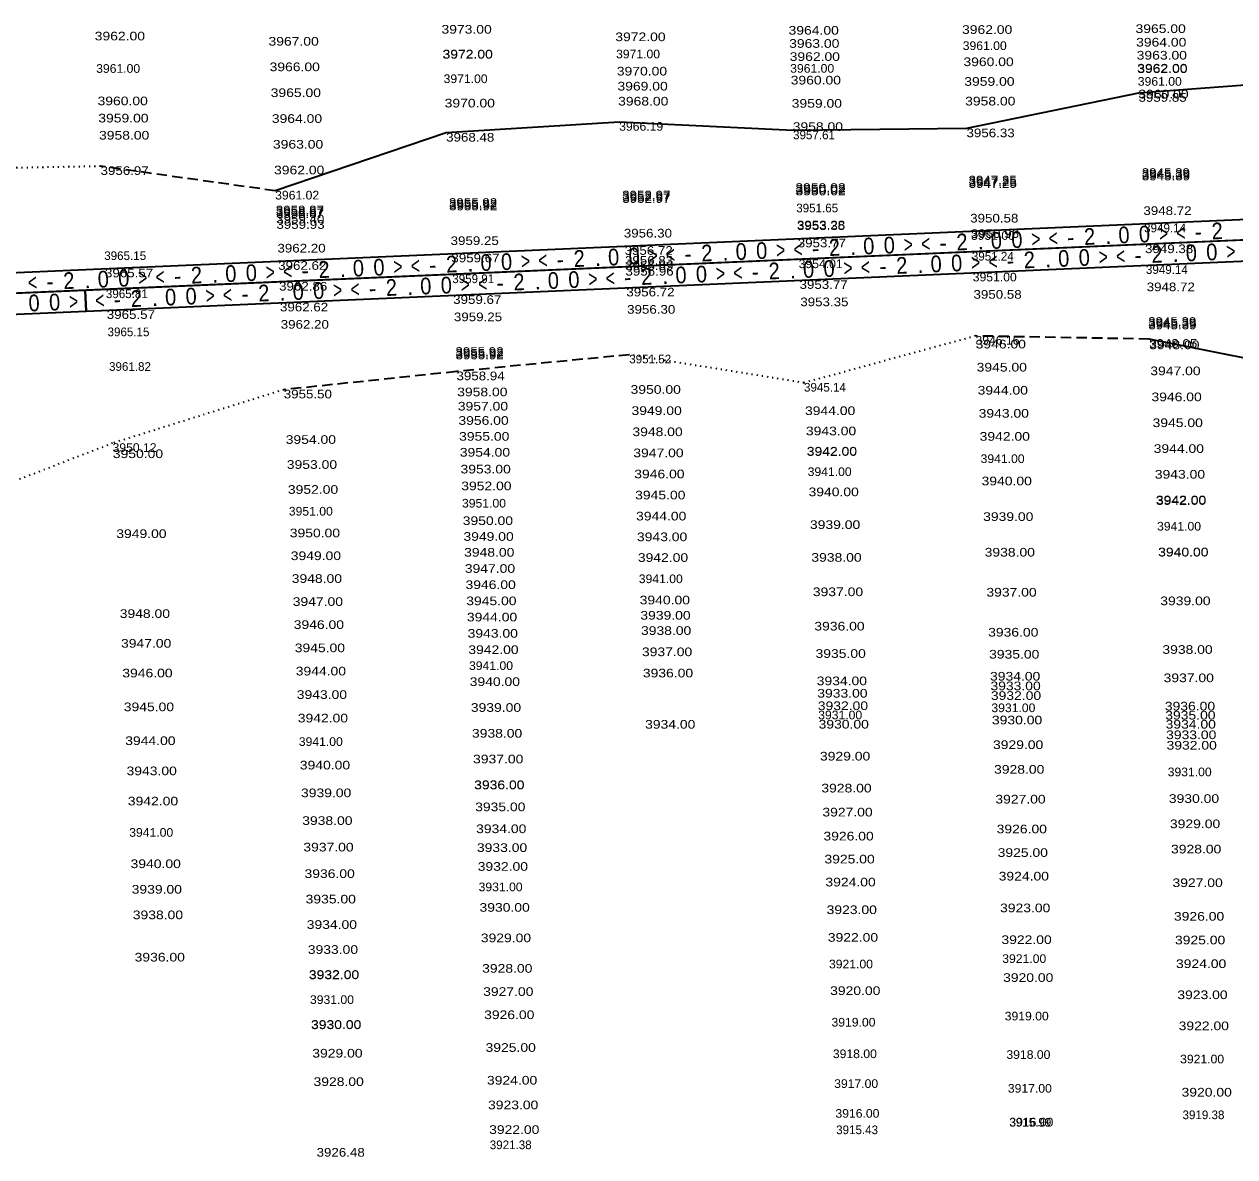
# Model space of a CAD drawing. Extents: x 49942 to 56479, y 47140 to 53283.
# Drawn here: x 52645 to 53343, y 49270 to 49923 of the extents above; entities that cross this region are included whole.
import ezdxf
from ezdxf.enums import TextEntityAlignment as Align

# ---------------------------------------------------------------- set-up
doc = ezdxf.new("R2010")
doc.units = 0
doc.header["$LTSCALE"] = 2
doc.linetypes.add('DOTTED', pattern=[1.5, 0.3, -1.2])
doc.linetypes.add('MEDIUM_DASHED', pattern=[4.5, 3, -1.5])
doc.layers.add('29', color=7, linetype='Continuous')
doc.layers.add('59', color=7, linetype='Continuous', lineweight=35)
doc.layers.add('63', color=7, linetype='Continuous', lineweight=35)

msp = doc.modelspace()

# ---------------------------------------------------------------- linework, layer by layer
at = {"layer": '59'}
for p, q in [((53387.529, 49890.602), (53287.754, 49883.256)), ((53287.754, 49883.256), (53188.546, 49862.795)), ((52988.196, 49866.565), (52888.374, 49860.274)), ((53088.503, 49861.631), (52988.196, 49866.565)), ((53188.546, 49862.795), (53088.503, 49861.631)), ((52888.374, 49860.274), (52789.726, 49826.892)), ((53394.861, 49721.266), (53293.897, 49741.36))]:
    msp.add_line(p, q, dxfattribs=at)
at = {"layer": '59', "linetype": 'DOTTED'}
for p, q in [((52689.019, 49841.052), (52589.011, 49839.074)), ((53193.726, 49743.159), (53094.804, 49716.091)), ((53094.804, 49716.091), (52994.006, 49732.374)), ((52794.693, 49712.17), (52695.936, 49681.3)), ((52695.936, 49681.3), (52597.493, 49643.178))]:
    msp.add_line(p, q, dxfattribs=at)
at = {"layer": '59', "linetype": 'MEDIUM_DASHED'}
for p, q in [((52789.726, 49826.892), (52689.019, 49841.052)), ((53293.897, 49741.36), (53193.726, 49743.159)), ((52994.006, 49732.374), (52894.334, 49722.632)), ((52894.334, 49722.632), (52794.693, 49712.17))]:
    msp.add_line(p, q, dxfattribs=at)
at = {"layer": '63'}
for points in [[(52494.091, 49773.45), (53576.866, 49820.33), (53577.385, 49808.342), (52494.61, 49761.461)], [(52680.665, 49757.505), (53728.923, 49802.891), (53728.404, 49814.88), (52680.146, 49769.494)]]:
    msp.add_lwpolyline(points, close=True, dxfattribs=at)
msp.add_lwpolyline([(52476.574, 49748.669), (52680.665, 49757.505), (52680.146, 49769.494), (52476.055, 49760.658)], dxfattribs=at)

# ---------------------------------------------------------------- texts
at = {"layer": '29'}
for s, width, p in [('3962.00', 1.2, (52685.659, 49913.662)), ('3973.00', 1.2, (52885.678, 49917.55)), ('3972.00', 1.2, (52985.959, 49913.218)), ('3964.00', 1.2, (53085.891, 49916.963)), ('3962.00', 1.2, (53185.965, 49917.411)), ('3965.00', 1.2, (53286.037, 49917.917)), ('3967.00', 1.2, (52785.884, 49910.637)), ('3963.00', 1.2, (53086.219, 49909.383)), ('3961.00', 1.05, (53186.367, 49908.114)), ('3964.00', 1.2, (53286.375, 49910.097)), ('3972.00', 1.2, (52886.296, 49903.27)), ('3972.00', 1.2, (52886.299, 49903.193)), ('3972.00', 1.2, (52886.303, 49903.117)), ('3971.00', 1.05, (52986.388, 49903.312)), ('3962.00', 1.2, (53086.547, 49901.804)), ('3960.00', 1.2, (53186.77, 49898.818)), ('3963.00', 1.2, (53286.7, 49902.597)), ('3961.00', 1.05, (52686.469, 49894.952)), ('3966.00', 1.2, (52786.521, 49895.901)), ('3970.00', 1.2, (52986.817, 49893.406)), ('3961.00', 1.05, (53086.841, 49895.019)), ('3962.00', 1.2, (53287.025, 49895.097)), ('3962.00', 1.2, (53287.031, 49894.963)), ('3962.00', 1.2, (53287.036, 49894.828)), ('3971.00', 1.05, (52886.912, 49889.051)), ('3969.00', 1.2, (52987.192, 49884.747)), ('3960.00', 1.2, (53087.135, 49888.233)), ('3959.00', 1.2, (53187.261, 49887.476)), ('3961.00', 1.05, (53287.354, 49887.5)), ('3965.00', 1.2, (52787.167, 49880.985)), ('3960.00', 1.2, (53287.671, 49880.172)), ('3959.85', 1.15, (53287.754, 49878.256)), ('3960.00', 1.2, (52687.279, 49876.241)), ('3970.00', 1.2, (52887.521, 49874.986)), ('3968.00', 1.2, (52987.567, 49876.089)), ('3959.00', 1.2, (53087.715, 49874.829)), ('3958.00', 1.2, (53187.752, 49876.133)), ('3959.00', 1.2, (52687.708, 49866.342)), ('3964.00', 1.2, (52787.813, 49866.069)), ('3958.00', 1.2, (52688.136, 49856.442)), ('3966.19', 1.05, (52988.196, 49861.565)), ('3958.00', 1.2, (53088.295, 49861.425)), ('3956.33', 1.15, (53188.546, 49857.795)), ('3963.00', 1.2, (52788.456, 49851.228)), ('3968.48', 1.15, (52888.374, 49855.274)), ('3956.97', 1.15, (52689.019, 49836.052)), ('3962.00', 1.2, (52789.098, 49836.388)), ('3945.39', 1.15, (53289.63, 49834.924)), ('3947.25', 1.15, (53189.724, 49830.598)), ('3947.25', 1.15, (53189.767, 49829.599)), ('3947.25', 1.15, (53189.81, 49828.6)), ('3945.39', 1.15, (53289.673, 49833.925)), ('3945.39', 1.15, (53289.717, 49832.926)), ('3961.02', 1.05, (52789.726, 49821.892)), ('3952.97', 1.15, (52989.911, 49821.947)), ('3952.97', 1.15, (52989.954, 49820.948)), ('3950.02', 1.2, (53089.817, 49826.273)), ('3950.02', 1.2, (53089.861, 49825.274)), ('3950.02', 1.2, (53089.904, 49824.275)), ('3955.92', 1.15, (52890.004, 49817.621)), ('3955.92', 1.15, (52890.048, 49816.622)), ('3955.92', 1.15, (52890.091, 49815.623)), ('3952.97', 1.15, (52989.997, 49819.949)), ('3958.87', 1.15, (52790.098, 49813.296)), ('3958.87', 1.15, (52790.141, 49812.297)), ('3958.87', 1.15, (52790.184, 49811.298)), ('3959.40', 1.15, (52790.322, 49808.129)), ('3950.58', 1.15, (53190.675, 49808.619)), ('3948.72', 1.15, (53290.582, 49812.944)), ('3959.93', 1.15, (52790.459, 49804.961)), ('3956.30', 1.15, (52990.862, 49799.968)), ('3953.28', 1.15, (53090.751, 49804.7)), ('3953.35', 1.15, (53090.769, 49804.293)), ('3959.25', 1.15, (52890.956, 49795.642)), ('3953.77', 1.15, (53091.201, 49794.303)), ('3950.96', 1.15, (53191.06, 49799.72)), ('3951.00', 1.05, (53191.108, 49798.628)), ('3962.20', 1.15, (52791.05, 49791.316)), ('3956.72', 1.15, (52991.295, 49789.977)), ('3949.38', 1.15, (53291.533, 49790.965)), ('3962.62', 1.15, (52791.482, 49781.326)), ('3959.67', 1.15, (52891.389, 49785.651)), ('3956.83', 1.15, (52991.54, 49784.317)), ('3956.89', 1.15, (52991.677, 49781.153)), ('3954.01', 1.05, (53091.721, 49782.314)), ('3965.57', 1.15, (52691.576, 49777)), ('3956.96', 1.15, (52991.814, 49777.988)), ('3951.00', 1.05, (53192.146, 49774.651)), ('3962.86', 1.15, (52792.001, 49769.337)), ('3956.72', 1.15, (52992.333, 49765.999)), ('3953.77', 1.15, (53092.24, 49770.325)), ('3948.72', 1.15, (53292.485, 49768.986)), ('3959.67', 1.15, (52892.427, 49761.674)), ('3953.35', 1.15, (53092.672, 49760.334)), ('3950.58', 1.15, (53192.578, 49764.66)), ('3965.57', 1.15, (52692.614, 49753.023)), ('3962.62', 1.15, (52792.52, 49757.348)), ('3959.25', 1.15, (52892.859, 49751.683)), ('3956.30', 1.15, (52992.766, 49756.009)), ('3962.20', 1.15, (52792.953, 49747.358)), ('3945.39', 1.15, (53293.35, 49749.004)), ('3945.39', 1.15, (53293.393, 49748.005)), ('3945.39', 1.15, (53293.437, 49747.006)), ('3946.16', 1.05, (53193.726, 49738.158)), ('3955.92', 1.15, (52893.724, 49731.702)), ('3955.92', 1.15, (52893.768, 49730.703)), ('3946.00', 1.2, (53193.821, 49735.97)), ('3948.05', 1.15, (53293.897, 49736.361)), ('3948.00', 1.2, (53293.933, 49735.547)), ('3955.92', 1.15, (52893.811, 49729.704)), ('3958.94', 1.15, (52894.334, 49717.632)), ('3945.00', 1.2, (53194.397, 49722.66)), ('3947.00', 1.2, (53294.582, 49720.541)), ('3950.00', 1.2, (52994.766, 49709.809)), ('3944.00', 1.2, (53194.973, 49709.349)), ('3955.50', 1.15, (52794.693, 49707.17)), ('3958.00', 1.2, (52894.734, 49708.385)), ('3946.00', 1.2, (53295.232, 49705.536)), ('3957.00', 1.2, (52895.09, 49700.151)), ('3949.00', 1.2, (52995.294, 49697.609)), ('3944.00', 1.2, (53095.39, 49697.561)), ('3943.00', 1.2, (53195.549, 49696.048)), ('3956.00', 1.2, (52895.447, 49691.917)), ('3945.00', 1.2, (53295.878, 49690.621)), ('3955.00', 1.2, (52895.844, 49682.752)), ('3948.00', 1.2, (52995.822, 49685.41)), ('3943.00', 1.2, (53095.896, 49685.88)), ('3942.00', 1.2, (53196.125, 49682.747)), ('3950.12', 1.05, (52695.936, 49676.3)), ('3954.00', 1.2, (52795.829, 49680.932)), ('3942.00', 1.2, (53096.402, 49674.198)), ('3944.00', 1.2, (53296.524, 49675.706)), ('3950.00', 1.2, (52696.09, 49672.746)), ('3954.00', 1.2, (52896.241, 49673.586)), ('3947.00', 1.2, (52996.349, 49673.238)), ('3942.00', 1.2, (53096.405, 49674.123)), ('3942.00', 1.2, (53096.409, 49674.029)), ('3941.00', 1.05, (53196.682, 49669.885)), ('3953.00', 1.2, (52796.453, 49666.527)), ('3953.00', 1.2, (52896.661, 49663.883)), ('3946.00', 1.2, (52996.876, 49661.066)), ('3941.00', 1.05, (53096.913, 49662.385)), ('3943.00', 1.2, (53297.165, 49660.897)), ('3952.00', 1.2, (52897.081, 49654.179)), ('3940.00', 1.2, (53197.239, 49657.023)), ('3952.00', 1.2, (52797.076, 49652.121)), ('3945.00', 1.2, (52997.402, 49648.919)), ('3940.00', 1.2, (53097.417, 49650.741)), ('3951.00', 1.05, (52797.619, 49639.583)), ('3951.00', 1.05, (52897.513, 49644.201)), ('3942.00', 1.2, (53297.806, 49646.087)), ('3942.00', 1.2, (53297.813, 49645.93)), ('3942.00', 1.2, (53297.821, 49645.754)), ('3950.00', 1.2, (52897.949, 49634.137)), ('3944.00', 1.2, (52997.928, 49636.774)), ('3939.00', 1.2, (53198.128, 49636.475)), ('3949.00', 1.2, (52698.086, 49626.637)), ('3950.00', 1.2, (52798.162, 49627.044)), ('3939.00', 1.2, (53098.235, 49631.846)), ('3941.00', 1.05, (53298.462, 49630.927)), ('3949.00', 1.2, (52898.344, 49625.013)), ('3943.00', 1.2, (52998.446, 49624.817)), ('3949.00', 1.2, (52798.731, 49613.899)), ('3948.00', 1.2, (52898.739, 49615.889)), ('3942.00', 1.2, (52998.964, 49612.86)), ('3938.00', 1.2, (53099.053, 49612.95)), ('3938.00', 1.2, (53199.018, 49615.927)), ('3940.00', 1.2, (53299.105, 49616.09)), ('3940.00', 1.2, (53299.107, 49616.029)), ('3940.00', 1.2, (53299.11, 49615.968)), ('3947.00', 1.2, (52899.143, 49606.55)), ('3948.00', 1.2, (52799.3, 49600.753)), ('3941.00', 1.05, (52999.494, 49600.61)), ('3946.00', 1.2, (52899.547, 49597.211)), ('3937.00', 1.2, (53099.912, 49593.115)), ('3937.00', 1.2, (53200.017, 49592.853)), ('3947.00', 1.2, (52799.876, 49587.467)), ('3945.00', 1.2, (52899.952, 49587.874)), ('3940.00', 1.2, (53000.024, 49588.36)), ('3939.00', 1.2, (53300.326, 49587.895)), ('3948.00', 1.2, (52700.082, 49580.529)), ('3944.00', 1.2, (52900.356, 49578.538)), ('3939.00', 1.2, (53000.406, 49579.551)), ('3946.00', 1.2, (52800.451, 49574.181)), ('3938.00', 1.2, (53000.787, 49570.742)), ('3936.00', 1.2, (53100.771, 49573.279)), ('3936.00', 1.2, (53201.016, 49569.78)), ('3947.00', 1.2, (52700.824, 49563.391)), ('3943.00', 1.2, (52900.763, 49569.136)), ('3945.00', 1.2, (52801.031, 49560.775)), ('3942.00', 1.2, (52901.17, 49559.735)), ('3937.00', 1.2, (53001.317, 49558.494)), ('3935.00', 1.2, (53101.454, 49557.504)), ('3935.00', 1.2, (53201.566, 49557.088)), ('3938.00', 1.2, (53301.541, 49559.821)), ('3941.00', 1.05, (52901.57, 49550.504)), ('3946.00', 1.2, (52701.566, 49546.253)), ('3944.00', 1.2, (52801.612, 49547.368)), ('3936.00', 1.2, (53001.848, 49546.247)), ('3934.00', 1.2, (53102.137, 49541.729)), ('3934.00', 1.2, (53202.115, 49544.396)), ('3937.00', 1.2, (53302.248, 49543.494)), ('3940.00', 1.2, (52901.969, 49541.273)), ('3933.00', 1.2, (53102.446, 49534.58)), ('3933.00', 1.2, (53202.357, 49538.822)), ('3943.00', 1.2, (52802.198, 49533.82)), ('3932.00', 1.2, (53202.598, 49533.248)), ('3945.00', 1.2, (52702.411, 49526.749)), ('3939.00', 1.2, (52902.614, 49526.377)), ('3932.00', 1.2, (53102.758, 49527.381)), ('3931.00', 1.05, (53102.989, 49522.051)), ('3931.00', 1.05, (53202.903, 49526.198)), ('3936.00', 1.2, (53302.955, 49527.167)), ('3935.00', 1.2, (53303.181, 49521.932)), ('3942.00', 1.2, (52802.785, 49520.271)), ('3934.00', 1.2, (53003.128, 49516.675)), ('3930.00', 1.2, (53103.22, 49516.72)), ('3930.00', 1.2, (53203.208, 49519.148)), ('3934.00', 1.2, (53303.408, 49516.697)), ('3944.00', 1.2, (52703.256, 49507.222)), ('3941.00', 1.05, (52803.372, 49506.711)), ('3938.00', 1.2, (52903.259, 49511.48)), ('3933.00', 1.2, (53303.671, 49510.637)), ('3929.00', 1.2, (53203.824, 49504.924)), ('3932.00', 1.2, (53303.933, 49504.578)), ('3940.00', 1.2, (52803.959, 49493.151)), ('3937.00', 1.2, (52903.901, 49496.658)), ('3929.00', 1.2, (53104.017, 49498.3)), ('3943.00', 1.2, (52704.01, 49489.816)), ('3928.00', 1.2, (53204.44, 49490.7)), ('3931.00', 1.05, (53304.598, 49489.215)), ('3936.00', 1.2, (52904.543, 49481.826)), ('3936.00', 1.2, (52904.546, 49481.753)), ('3936.00', 1.2, (52904.55, 49481.68)), ('3928.00', 1.2, (53104.815, 49479.881)), ('3942.00', 1.2, (52704.764, 49472.41)), ('3939.00', 1.2, (52804.652, 49477.147)), ('3927.00', 1.2, (53205.185, 49473.499)), ('3930.00', 1.2, (53305.263, 49473.852)), ('3935.00', 1.2, (52905.096, 49469.052)), ('3927.00', 1.2, (53105.415, 49466.03)), ('3938.00', 1.2, (52805.345, 49461.142)), ('3929.00', 1.2, (53305.894, 49459.281)), ('3941.00', 1.05, (52705.546, 49454.328)), ('3934.00', 1.2, (52905.643, 49456.425)), ('3926.00', 1.2, (53106.014, 49452.18)), ('3926.00', 1.2, (53205.93, 49456.298)), ('3937.00', 1.2, (52806.007, 49445.843)), ('3933.00', 1.2, (52906.113, 49445.559)), ('3928.00', 1.2, (53306.525, 49444.711)), ('3925.00', 1.2, (53106.588, 49438.932)), ('3925.00', 1.2, (53206.518, 49442.695)), ('3940.00', 1.2, (52706.329, 49436.246)), ('3936.00', 1.2, (52806.67, 49430.543)), ('3932.00', 1.2, (52906.584, 49434.694)), ('3931.00', 1.05, (52907.095, 49422.882)), ('3924.00', 1.2, (53107.161, 49425.684)), ('3924.00', 1.2, (53207.108, 49429.093)), ('3927.00', 1.2, (53307.365, 49425.316)), ('3939.00', 1.2, (52706.967, 49421.508)), ('3935.00', 1.2, (52807.306, 49415.862)), ('3930.00', 1.2, (52907.607, 49411.07)), ('3923.00', 1.2, (53107.852, 49409.728)), ('3923.00', 1.2, (53207.901, 49410.774)), ('3938.00', 1.2, (52707.606, 49406.769)), ('3926.00', 1.2, (53308.204, 49405.921)), ('3934.00', 1.2, (52807.941, 49401.181)), ('3929.00', 1.2, (52908.368, 49393.486)), ('3922.00', 1.2, (53108.543, 49393.772)), ('3922.00', 1.2, (53208.694, 49392.455)), ('3925.00', 1.2, (53308.796, 49392.26)), ('3936.00', 1.2, (52708.662, 49382.369)), ('3933.00', 1.2, (52808.565, 49386.774)), ('3921.00', 1.05, (53209.167, 49381.529)), ('3928.00', 1.2, (52909.129, 49375.903)), ('3921.00', 1.05, (53109.208, 49378.413)), ('3924.00', 1.2, (53309.387, 49378.599)), ('3932.00', 1.2, (52809.189, 49372.367)), ('3932.00', 1.2, (52809.193, 49372.275)), ('3932.00', 1.2, (52809.197, 49372.167)), ('3920.00', 1.2, (53209.64, 49370.602)), ('3927.00', 1.2, (52909.709, 49362.528)), ('3920.00', 1.2, (53109.873, 49363.054)), ('3923.00', 1.2, (53310.163, 49360.677)), ('3931.00', 1.05, (52809.817, 49357.869)), ('3926.00', 1.2, (52910.287, 49349.153)), ('3919.00', 1.05, (53210.601, 49348.395)), ('3930.00', 1.2, (52810.435, 49343.572)), ('3930.00', 1.2, (52810.439, 49343.487)), ('3930.00', 1.2, (52810.444, 49343.373)), ('3919.00', 1.05, (53110.661, 49344.849)), ('3922.00', 1.2, (53310.939, 49342.755)), ('3929.00', 1.2, (52811.154, 49326.971)), ('3925.00', 1.2, (52911.105, 49330.263)), ('3918.00', 1.05, (53111.45, 49326.643)), ('3918.00', 1.05, (53211.563, 49326.187)), ('3921.00', 1.05, (53311.768, 49323.615)), ('3924.00', 1.2, (52911.923, 49311.374)), ('3928.00', 1.2, (52811.864, 49310.569)), ('3917.00', 1.05, (53112.194, 49309.453)), ('3917.00', 1.05, (53212.406, 49306.708)), ('3920.00', 1.2, (53312.597, 49304.475)), ('3923.00', 1.2, (52912.539, 49297.144)), ('3916.00', 1.05, (53112.938, 49292.262)), ('3916.00', 1.05, (53213.25, 49287.229)), ('3922.00', 1.2, (52913.156, 49282.914)), ('3926.48', 1.15, (52813.629, 49269.805))]:
    msp.add_text(s, height=5, dxfattribs=dict(at, width=width)).set_placement(p)
for s, p in [('3957.61', (53088.503, 49856.631)), ('3951.65', (53090.328, 49814.487)), ('3949.14', (53291.014, 49802.954)), ('3965.15', (52691.143, 49786.991)), ('3951.24', (53191.627, 49786.639)), ('3949.14', (53292.052, 49778.976)), ('3959.91', (52891.908, 49773.663)), ('3965.81', (52692.095, 49765.011)), ('3965.15', (52693.047, 49743.032)), ('3951.52', (52994.006, 49727.374)), ('3961.82', (52693.912, 49723.051)), ('3945.14', (53094.804, 49711.09)), ('3919.38', (53313.161, 49291.433)), ('3915.99', (53213.255, 49287.108)), ('3915.43', (53113.349, 49282.782)), ('3921.38', (52913.536, 49274.131))]:
    msp.add_text(s, height=5, dxfattribs=at).set_placement(p)
at = {"layer": '63'}
for s, width, p in [('2', 0.9, (53259.758, 49795.791)), ('0', 0.9, (53279.582, 49796.649)), ('0', 0.9, (53291.413, 49797.161)), ('>', 0.7, (53302.348, 49797.635)), ('<', 0.7, (53312.385, 49798.069)), ('2', 0.9, (53333.358, 49798.977)), ('2', 0.9, (53112.557, 49789.417)), ('0', 0.9, (53132.381, 49790.276)), ('0', 0.9, (53144.212, 49790.788)), ('>', 0.7, (53155.147, 49791.261)), ('<', 0.7, (53165.185, 49791.696)), ('2', 0.9, (53186.157, 49792.604)), ('0', 0.9, (53205.981, 49793.462)), ('0', 0.9, (53217.813, 49793.974)), ('>', 0.7, (53228.747, 49794.448)), ('<', 0.7, (53238.785, 49794.882)), ('0', 0.9, (52923.411, 49781.228)), ('2', 0.9, (52965.356, 49783.044)), ('0', 0.9, (52985.18, 49783.902)), ('0', 0.9, (52997.012, 49784.414)), ('>', 0.7, (53007.946, 49784.888)), ('<', 0.7, (53017.984, 49785.323)), ('2', 0.9, (53038.957, 49786.231)), ('0', 0.9, (53058.781, 49787.089)), ('0', 0.9, (53070.612, 49787.601)), ('>', 0.7, (53081.547, 49788.075)), ('<', 0.7, (53091.584, 49788.509)), ('2', 0.9, (53225.012, 49782.275)), ('0', 0.9, (53244.836, 49783.133)), ('0', 0.9, (53256.667, 49783.645)), ('>', 0.7, (53267.602, 49784.119)), ('<', 0.7, (53277.64, 49784.554)), ('2', 0.9, (53298.612, 49785.461)), ('0', 0.9, (53318.436, 49786.32)), ('0', 0.9, (53330.268, 49786.832)), ('>', 0.7, (53341.202, 49787.306)), ('0', 0.9, (52764.379, 49774.342)), ('0', 0.9, (52776.211, 49774.855)), ('2', 0.9, (52818.156, 49776.671)), ('0', 0.9, (52837.979, 49777.529)), ('0', 0.9, (52849.811, 49778.041)), ('>', 0.7, (52860.746, 49778.515)), ('<', 0.7, (52870.783, 49778.949)), ('2', 0.9, (52891.756, 49779.857)), ('0', 0.9, (52911.58, 49780.716)), ('>', 0.7, (52934.346, 49781.701)), ('<', 0.7, (52944.384, 49782.136)), ('2', 0.9, (53077.811, 49775.901)), ('0', 0.9, (53097.635, 49776.76)), ('0', 0.9, (53109.467, 49777.272)), ('>', 0.7, (53120.401, 49777.746)), ('<', 0.7, (53130.439, 49778.18)), ('2', 0.9, (53151.411, 49779.088)), ('0', 0.9, (53171.235, 49779.946)), ('0', 0.9, (53183.067, 49780.459)), ('>', 0.7, (53194.001, 49780.932)), ('<', 0.7, (53204.039, 49781.367)), ('<', 0.7, (52649.982, 49769.389)), ('2', 0.9, (52670.955, 49770.297)), ('0', 0.9, (52690.779, 49771.156)), ('0', 0.9, (52702.61, 49771.668)), ('>', 0.7, (52713.545, 49772.141)), ('<', 0.7, (52723.583, 49772.576)), ('2', 0.9, (52744.555, 49773.484)), ('>', 0.7, (52787.145, 49775.328)), ('<', 0.7, (52797.183, 49775.763)), ('0', 0.9, (52888.666, 49767.712)), ('2', 0.9, (52930.61, 49769.528)), ('0', 0.9, (52950.434, 49770.387)), ('0', 0.9, (52962.266, 49770.899)), ('>', 0.7, (52973.2, 49771.372)), ('<', 0.7, (52983.238, 49771.807)), ('2', 0.9, (53004.211, 49772.715)), ('0', 0.9, (53024.035, 49773.573)), ('0', 0.9, (53035.866, 49774.085)), ('>', 0.7, (53046.801, 49774.559)), ('<', 0.7, (53056.839, 49774.994)), ('0', 0.9, (52729.633, 49760.827)), ('0', 0.9, (52741.465, 49761.339)), ('<', 0.7, (52762.437, 49762.247)), ('2', 0.9, (52783.41, 49763.155)), ('0', 0.9, (52803.234, 49764.013)), ('0', 0.9, (52815.065, 49764.526)), ('>', 0.7, (52826, 49764.999)), ('<', 0.7, (52836.038, 49765.434)), ('2', 0.9, (52857.01, 49766.342)), ('0', 0.9, (52876.834, 49767.2)), ('>', 0.7, (52899.6, 49768.186)), ('<', 0.7, (52909.638, 49768.62)), ('0', 0.9, (52650.876, 49757.417)), ('0', 0.9, (52662.708, 49757.929)), ('>', 0.7, (52673.643, 49758.402)), ('<', 0.7, (52688.837, 49759.06)), ('2', 0.9, (52709.809, 49759.968)), ('>', 0.7, (52752.399, 49761.812))]:
    msp.add_text(s, height=9.6, rotation=2.479, dxfattribs=dict(at, width=width)).set_placement(p, align=Align.CENTER)
for s, p in [('-', (53248.823, 49795.317)), ('-', (53322.423, 49798.504)), ('-', (53101.622, 49788.944)), ('.', (53123.272, 49789.881)), ('-', (53175.223, 49792.13)), ('.', (53196.872, 49793.068)), ('.', (53270.473, 49796.254)), ('-', (52954.422, 49782.57)), ('.', (52976.071, 49783.508)), ('-', (53028.022, 49785.757)), ('.', (53049.672, 49786.694)), ('-', (53214.077, 49781.801)), ('.', (53235.727, 49782.739)), ('-', (53287.678, 49784.988)), ('.', (53309.327, 49785.925)), ('-', (52733.621, 49773.011)), ('-', (52807.221, 49776.197)), ('.', (52828.871, 49777.134)), ('-', (52880.821, 49779.384)), ('.', (52902.471, 49780.321)), ('-', (53066.876, 49775.428)), ('.', (53088.526, 49776.365)), ('-', (53140.477, 49778.615)), ('.', (53162.127, 49779.552)), ('-', (52660.02, 49769.824)), ('.', (52681.67, 49770.761)), ('.', (52755.27, 49773.948)), ('-', (52846.075, 49765.868)), ('-', (52919.676, 49769.055)), ('.', (52941.326, 49769.992)), ('-', (52993.276, 49772.241)), ('.', (53014.926, 49773.179)), ('-', (52698.875, 49759.495)), ('-', (52772.475, 49762.682)), ('.', (52794.125, 49763.619)), ('.', (52867.725, 49766.805)), ('.', (52720.525, 49760.432))]:
    msp.add_text(s, height=9.6, rotation=2.479, dxfattribs=at).set_placement(p, align=Align.CENTER)

doc.saveas('drawing.dxf')
